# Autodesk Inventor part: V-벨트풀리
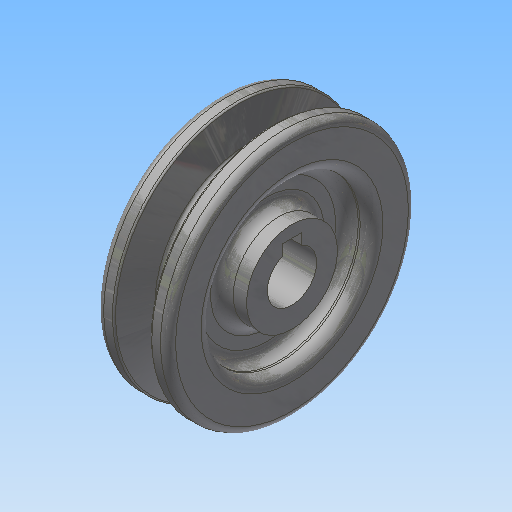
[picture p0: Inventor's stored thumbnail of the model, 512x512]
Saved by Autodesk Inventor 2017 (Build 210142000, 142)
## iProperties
Created: 2015-12
Part Number: V-벨트풀리
Material: 강철, 연강
Document SubType Name: Modeling
Designer: mduedu
Density: 7.86 g/cm^3
Appearance: 강철
Author: mduedu
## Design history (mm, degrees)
sketch "스케치1"
  geometry: L1 (-9.5, 0)-(9.5, 0); L2 (-9.5, 0)-(-9.5, 32.7); L3 (-9.5, 32.7)-(-4.825, 32.7); L4 (-4.825, 32.7)-(-2.074, 23.7); L5 (-2.074, 23.7)-(0, 23.7); L6 (0, 0)-(0, 23.7); L7 (9.5, 0)-(9.5, 32.7); L8 (9.5, 32.7)-(4.825, 32.7); L9 (4.825, 32.7)-(2.074, 23.7); L10 (2.074, 23.7)-(0, 23.7); L11 (-4, 30)-(4, 30); 3 further points
  constraints: 22 end point, 3 coincident, 3 perpendicular, 3 symmetric about line, 2 parallel, 2 point on line, 1 horizontal, 1 midpoint, 1 vertical alignment
  dimensions: "d0" = 19 distance between parallel lines of L7 L2; "d2" = 6.3 distance between parallel lines of L10 L11; "d3" = 34 deg angle of L9 L4; "d4" = 2.7 distance between parallel lines of L11 L8; "d5" = 60 diameter of L11 L1; "d6" = 8 distance of L11.end L11.start
revolve "회전1" sketch "스케치1" stored, may be unused: angle "d7" = 90 deg
sketch "스케치2"
  geometry: C1 r 21 at (0, 0); C2 r 12 at (0, 0); 1 further point
  constraints: 2 centre point, 2 coincident
  dimensions: "d8" = 42 diameter of C1; "d10" = 24 diameter of C2
extrude "돌출1" cut sketch "스케치2" distance "d11" = 6.5; taper "d12" = 0 deg
fillet "모깎기1" dims "d13" = 1, "d14" = 0.5, "d15" = 2
fillet "모깎기2" dims "d16" = 3
fillet "모깎기3" dims "d17" = 3
hole "구멍1" diameter "d20" = 13; stored, may be unused: countersink angle "d24" = 90 deg, drill point angle "d26" = 118 deg; dims "d18" = 10, "d19" = 10, "d21" = 6, "d22" = 4, "d23" = 2, "d25" = 8
sketch "스케치3"
  geometry: L1 (-2.5, 0)-(2.5, 0); L2 (2.5, 0)-(2.5, 8.8); L3 (2.5, 8.8)-(-2.5, 8.8); L4 (-2.5, 8.8)-(-2.5, 0); 2 further points
  constraints: 8 end point, 2 parallel, 1 coincident, 1 horizontal, 1 midpoint, 1 perpendicular
  dimensions: "d27" = 8.8 distance of L1.end L2.end; "d29" = 5 distance of L2.end L3.end
extrude "돌출2" cut sketch "스케치3" stored distance "d30" = 6.5; taper "d31" = 0 deg
node "솔리드1"
mirror "대칭1"
